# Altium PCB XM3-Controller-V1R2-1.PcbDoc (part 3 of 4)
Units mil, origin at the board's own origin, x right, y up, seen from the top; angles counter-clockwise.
Board outline 10629.92 x 4173.11 mil, 6 copper layers (TOP, GND1, LAYER3, PWR, GND2, BOTTOM), stack 62 mil thick; 362 components, 276 nets, 1145 pads, 503 vias.
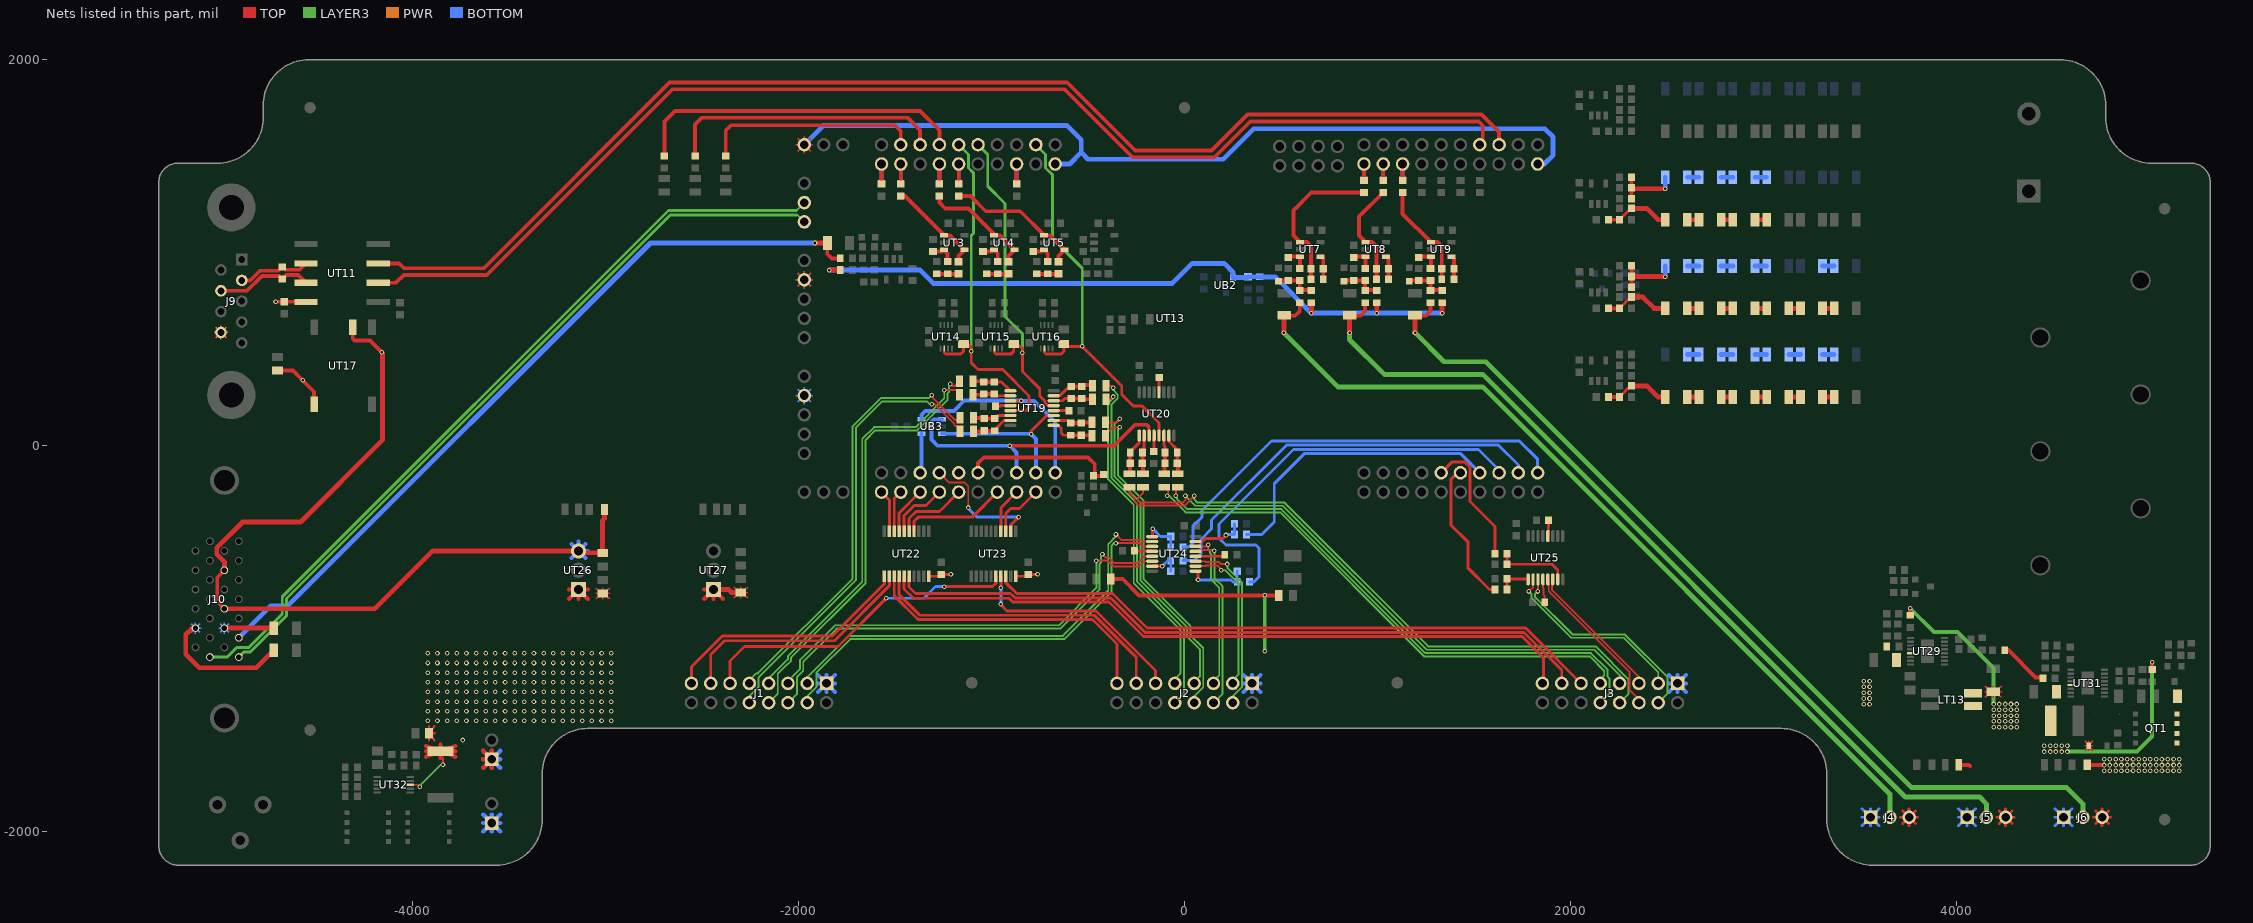
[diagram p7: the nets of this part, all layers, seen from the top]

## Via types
v1: diameter 24, hole 13, TOP to BOTTOM, 503 vias

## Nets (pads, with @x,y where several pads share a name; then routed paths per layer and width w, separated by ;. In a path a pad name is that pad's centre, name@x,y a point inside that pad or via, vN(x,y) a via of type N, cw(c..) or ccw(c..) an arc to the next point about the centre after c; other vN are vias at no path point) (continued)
+3VREF: CB15.1 RB20.1 RT49.1 RT63.1 RT65.1 RT67.1 UB2.2 | length 3589.5
  TOP w25: v1(-1840,910) -1839.36,910.64 -1837.69,910.64 RT49.1@-1784,910.64 ; v1(657.5,687.5) RT63.1@657.5,741.19 ; v1(996.02,687.5) RT65.1@996.02,741.19 ; v1(1334.54,687.5) RT67.1@1334.54,741.19
  BOTTOM w25: v1(-1840,910) -1369.99,910 -1299.99,840 -65,840 40,945 205,945 251.25,898.75 UB2.2@251.25,872.16 325.75,872.16 CB15.1@329.25,875.66 RB20.1@389.25,875.66 389.91,875 470,875 v1(657.5,687.5) v1(996.02,687.5) v1(1334.54,687.5)
+5V: CT63.1 CT65.1 CT66.1 J10.12 J10.20 RT109.1 UT13.21 UT13.61 UT13.92 UT13.97 UT13.105 UT17.2 UT22.20 UT23.20 UT26.3 | length 10975.7
  TOP w7: -2014.02,860 UT13.97@-1970,860 ; -2014.02,1560 UT13.105@-1970,1560 ; -2003.13,826.87 UT13.97@-1970,860 ; -2003.13,893.13 UT13.97@-1970,860 ; -2003.13,1526.87 UT13.105@-1970,1560 ; -2003.13,1593.13 UT13.105@-1970,1560 ; -1970,815.98 UT13.97@-1970,860 ; -1970,904.02 UT13.97@-1970,860 ; -1970,1515.98 UT13.105@-1970,1560 ; -1970,1604.02 UT13.105@-1970,1560 ; -1936.87,826.87 UT13.97@-1970,860 ; -1936.87,893.13 UT13.97@-1970,860 ; -1936.87,1526.87 UT13.105@-1970,1560 ; -1936.87,1593.13 UT13.105@-1970,1560 ; -1925.98,860 UT13.97@-1970,860 ; -1925.98,1560 UT13.105@-1970,1560
  TOP w15: UT22.20@-1324.84,-676.14 -1269.64,-676.14 CT65.1@-1260,-666.5 v1(-1210,-666.5) ; UT23.20@-874.84,-676.14 -819.64,-676.14 CT66.1@-810,-666.5 v1(-761.5,-666.5)
  TOP w20: J10.12@-4975,-845 -5012,-808 -5012,-682 J10.20@-4975,-645 ; UT17.2@-4310,615 -4310,555 -4300,545 -4220,545 v1(-4160,485)
  TOP w25: J10.12@-4975,-845 -4195,-845 -3895,-545 UT26.3@-3140.47,-545 -3130.9,-554.57 CT63.1@-3015,-554.57 -3015,-386.43 -3005.63,-377.06 RT109.1@-3005.63,-330 ; J10.20@-4975,-645 -4975,-600.87 -5014.5,-561.37 -5014.5,-528.63 -4880.87,-395 -4580,-395 -4155,30 -4155,480 v1(-4160,485)
  BOTTOM w7: -2014.02,260 UT13.92@-1970,260 ; -2014.02,860 UT13.97@-1970,860 ; -2003.13,226.87 UT13.92@-1970,260 ; -2003.13,293.13 UT13.92@-1970,260 ; -2003.13,826.87 UT13.97@-1970,860 ; -2003.13,893.13 UT13.97@-1970,860 ; -1970,215.98 UT13.92@-1970,260 ; -1970,304.02 UT13.92@-1970,260 ; -1970,815.98 UT13.97@-1970,860 ; -1970,904.02 UT13.97@-1970,860 ; -1936.87,226.87 UT13.92@-1970,260 ; -1936.87,293.13 UT13.92@-1970,260 ; -1936.87,826.87 UT13.97@-1970,860 ; -1936.87,893.13 UT13.97@-1970,860 ; -1925.98,260 UT13.92@-1970,260 ; -1925.98,860 UT13.97@-1970,860
  BOTTOM w22: -3188.86,-545 UT26.3@-3140.47,-545 ; -3176.69,-581.22 UT26.3@-3140.47,-545 ; -3176.69,-508.78 UT26.3@-3140.47,-545 ; -3140.47,-496.61 UT26.3@-3140.47,-545 ; -3104.25,-581.22 UT26.3@-3140.47,-545 ; -3104.25,-508.78 UT26.3@-3140.47,-545 ; -3092.08,-545 UT26.3@-3140.47,-545
  BOTTOM w25: UT13.105@-1970,1560 -1870,1660 -610,1660 -535,1585 -535,1520 ; UT13.61@-670,1460 -595,1460 -535,1520 ; UT13.21@1830,1460 1865,1460 1910,1505 1910,1600 1867.32,1642.68 357.68,1642.68 200,1485 -500,1485 -535,1520
+5V-ISO: CT37.1 CT47.1 J9.9 UT11.8 UT17.5 | length 766
  TOP w20: v1(-4710,746.5) CT37.1@-4665,746.5 -4554,746.5 UT11.8@-4552.5,745 ; CT47.1@-4700,389.57 -4619.57,389.57 v1(-4569.47,339.47) -4510,280 UT17.5@-4510,215 UT17.5@-4510,195
  PWR w7: -5027.52,587 J9.9@-4993,587 ; -5019.41,560.59 J9.9@-4993,587 ; -5019.41,613.41 J9.9@-4993,587 ; -4993,552.48 J9.9@-4993,587 ; -4993,621.52 J9.9@-4993,587 ; -4966.59,560.59 J9.9@-4993,587 ; -4966.59,613.41 J9.9@-4993,587 ; -4958.48,587 J9.9@-4993,587
+12V: CT68.1 CT70.1 CT78.1 CT83.1 CT86.1 DT10.A J1.1 J2.1 J3.1 J12.1 J13.1 LT13.1 LT14.1 RT116.1 RT119.1 RT125.1 RT128.2 RT132.2 RT133.1 RT141.2 UT26.1 UT27.1 UT29.5 UT31.5 UT32.8 | length 7205.2
  TOP w7: -3051.58,-792.87 CT70.1@-3015,-765.43 ; -3051.58,-765.43 CT70.1@-3015,-765.43 ; -3051.58,-737.99 CT70.1@-3015,-765.43 ; -3015,-795.12 CT70.1@-3015,-765.43 ; -3015,-735.74 CT70.1@-3015,-765.43 ; -2978.42,-792.87 CT70.1@-3015,-765.43 ; -2978.42,-765.43 CT70.1@-3015,-765.43 ; -2978.42,-737.99 CT70.1@-3015,-765.43 ; -2336.58,-787.87 CT68.1@-2300,-760.43 ; -2336.58,-732.99 CT68.1@-2300,-760.43 ; -2300,-790.12 CT68.1@-2300,-760.43 ; -2300,-730.74 CT68.1@-2300,-760.43 ; -2263.42,-787.87 CT68.1@-2300,-760.43 ; -2263.42,-760.43 CT68.1@-2300,-760.43 ; -2263.42,-732.99 CT68.1@-2300,-760.43 ; 4664.48,-1555 DT10.A@4686,-1555 ; 4666.66,-1580.52 DT10.A@4686,-1555 ; 4666.66,-1529.48 DT10.A@4686,-1555 ; 4686,-1580.52 DT10.A@4686,-1555 ; 4686,-1529.48 DT10.A@4686,-1555 ; 4705.34,-1580.52 DT10.A@4686,-1555 ; 4705.34,-1529.48 DT10.A@4686,-1555 ; 4707.52,-1555 DT10.A@4686,-1555
  TOP w10: UT32.8@-4012.5,-1756.67 -3972.5,-1756.67 v1(-3962.5,-1766.67) ; v1(-3842.5,-1653.33) -3842.5,-1618.2
  TOP w12: -3914.57,-1526.58 CT86.1@-3914.57,-1490 ; -3914.57,-1453.42 CT86.1@-3914.57,-1490 ; -3887.13,-1526.58 CT86.1@-3914.57,-1490 ; -3887.13,-1453.42 CT86.1@-3914.57,-1490 ; -3884.88,-1490 CT86.1@-3914.57,-1490
  TOP w20: RT116.1@-382.6,-690 -320,-690 -235,-775 v1(416.11,-775) RT119.1@487.6,-775 ; RT128.2@4250.5,-1059 4269,-1059 4410,-1200 4443.5,-1200 RT133.1@4448.5,-1205 ; RT132.2@5014,-1159.5 v1(5014,-1121)
  TOP w22: -3930.95,-1611.18 RT141.2@-3855,-1583.25 ; -3930.95,-1583.25 RT141.2@-3855,-1583.25 ; -3930.95,-1555.32 RT141.2@-3855,-1583.25 ; -3855,-1616.88 RT141.2@-3855,-1583.25 ; -3855,-1549.62 RT141.2@-3855,-1583.25 ; -3779.05,-1611.18 RT141.2@-3855,-1583.25 ; -3779.05,-1583.25 RT141.2@-3855,-1583.25 ; -3779.05,-1555.32 RT141.2@-3855,-1583.25 ; -3634.02,-1669.02 J13.1@-3590,-1625 ; -3634.02,-1625 J13.1@-3590,-1625 ; -3634.02,-1580.98 J13.1@-3590,-1625 ; -3590,-1669.02 J13.1@-3590,-1625 ; -3590,-1580.98 J13.1@-3590,-1625 ; -3188.86,-793.39 UT26.1@-3140.47,-745 ; -3188.86,-745 UT26.1@-3140.47,-745 ; -3140.47,-793.39 UT26.1@-3140.47,-745 ; -3092.08,-793.39 UT26.1@-3140.47,-745 ; -3092.08,-745 UT26.1@-3140.47,-745 ; -2488.86,-793.39 UT27.1@-2440.47,-745 ; -2488.86,-745 UT27.1@-2440.47,-745 ; -2440.47,-793.39 UT27.1@-2440.47,-745 ; -2392.08,-793.39 UT27.1@-2440.47,-745
  TOP w25: UT27.1@-2440.47,-745 -2362.49,-745 -2347.06,-760.43 CT68.1@-2300,-760.43
  LAYER3 w10: v1(-3962.5,-1766.67) -3962.5,-1761.67 -3854.16,-1653.33 v1(-3842.5,-1653.33)
  LAYER3 w20: v1(416.11,-1063.89) v1(416.11,-775) ; v1(4575.37,-1584.56) 4575.81,-1585 4935,-1585 5014,-1506 v1(5014,-1121)
  BOTTOM w22: -3634.02,-1999.02 J12.1@-3590,-1955 ; -3634.02,-1955 J12.1@-3590,-1955 ; -3634.02,-1910.98 J12.1@-3590,-1955 ; -3634.02,-1669.02 J13.1@-3590,-1625 ; -3634.02,-1625 J13.1@-3590,-1625 ; -3634.02,-1580.98 J13.1@-3590,-1625 ; -3590,-1999.02 J12.1@-3590,-1955 ; -3590,-1910.98 J12.1@-3590,-1955 ; -3590,-1669.02 J13.1@-3590,-1625 ; -3590,-1580.98 J13.1@-3590,-1625 ; -3545.98,-1999.02 J12.1@-3590,-1955 ; -3545.98,-1955 J12.1@-3590,-1955 ; -3545.98,-1910.98 J12.1@-3590,-1955 ; -3545.98,-1669.02 J13.1@-3590,-1625 ; -3545.98,-1625 J13.1@-3590,-1625 ; -3545.98,-1580.98 J13.1@-3590,-1625 ; -1898.74,-1275.38 J1.1@-1854.72,-1231.36 ; -1898.74,-1231.36 J1.1@-1854.72,-1231.36 ; -1898.74,-1187.34 J1.1@-1854.72,-1231.36 ; -1854.72,-1275.38 J1.1@-1854.72,-1231.36 ; -1854.72,-1187.34 J1.1@-1854.72,-1231.36 ; -1810.7,-1275.38 J1.1@-1854.72,-1231.36 ; -1810.7,-1231.36 J1.1@-1854.72,-1231.36 ; -1810.7,-1187.34 J1.1@-1854.72,-1231.36 ; 305.98,-1275.38 J2.1@350,-1231.36 ; 305.98,-1231.36 J2.1@350,-1231.36 ; 305.98,-1187.34 J2.1@350,-1231.36 ; 350,-1275.38 J2.1@350,-1231.36 ; 350,-1187.34 J2.1@350,-1231.36 ; 394.02,-1275.38 J2.1@350,-1231.36 ; 394.02,-1231.36 J2.1@350,-1231.36 ; 394.02,-1187.34 J2.1@350,-1231.36 ; 2510.7,-1275.38 J3.1@2554.72,-1231.36 ; 2510.7,-1231.36 J3.1@2554.72,-1231.36 ; 2510.7,-1187.34 J3.1@2554.72,-1231.36 ; 2554.72,-1275.38 J3.1@2554.72,-1231.36 ; 2554.72,-1187.34 J3.1@2554.72,-1231.36 ; 2598.74,-1275.38 J3.1@2554.72,-1231.36 ; 2598.74,-1231.36 J3.1@2554.72,-1231.36 ; 2598.74,-1187.34 J3.1@2554.72,-1231.36
  other v1: 4455.37,-1584.56 4485.37,-1584.56 4515.37,-1584.56 4545.37,-1584.56 4455.37,-1554.56 4485.37,-1554.56 4515.37,-1554.56 4545.37,-1554.56 4575.37,-1554.56 -3740,-1525 -3920.82,-1425.62 -3870.82,-1425.62 -3820.82,-1425.62 -3770.82,-1425.62 -3720.82,-1425.62 -3670.82,-1425.62 -3620.82,-1425.62 -3570.82,-1425.62 -3520.82,-1425.62 -3470.82,-1425.62 -3420.82,-1425.62 -3370.82,-1425.62 -3320.82,-1425.62 -3270.82,-1425.62 -3220.82,-1425.62 -3170.82,-1425.62 -3120.82,-1425.62 -3070.82,-1425.62 -3020.82,-1425.62 -2970.82,-1425.62 -3920.82,-1375.62 -3870.82,-1375.62 -3820.82,-1375.62 -3770.82,-1375.62 -3720.82,-1375.62 -3670.82,-1375.62 -3620.82,-1375.62 -3570.82,-1375.62 -3520.82,-1375.62 -3470.82,-1375.62 -3420.82,-1375.62 -3370.82,-1375.62 -3320.82,-1375.62 -3270.82,-1375.62 -3220.82,-1375.62 -3170.82,-1375.62 -3120.82,-1375.62 -3070.82,-1375.62 -3020.82,-1375.62 -2970.82,-1375.62 3519.56,-1339.63 3549.56,-1339.63 -3920.82,-1325.62 -3870.82,-1325.62 -3820.82,-1325.62 -3770.82,-1325.62 -3720.82,-1325.62 -3670.82,-1325.62 -3620.82,-1325.62 -3570.82,-1325.62 -3520.82,-1325.62 -3470.82,-1325.62 -3420.82,-1325.62 -3370.82,-1325.62 -3320.82,-1325.62 -3270.82,-1325.62 -3220.82,-1325.62 -3170.82,-1325.62 -3120.82,-1325.62 -3070.82,-1325.62 -3020.82,-1325.62 -2970.82,-1325.62 3519.56,-1309.63 3549.56,-1309.63 3519.56,-1279.63 3549.56,-1279.63 -3920.82,-1275.62 -3870.82,-1275.62 -3820.82,-1275.62 -3770.82,-1275.62 -3720.82,-1275.62 -3670.82,-1275.62 -3620.82,-1275.62 -3570.82,-1275.62 -3520.82,-1275.62 -3470.82,-1275.62 -3420.82,-1275.62 -3370.82,-1275.62 -3320.82,-1275.62 -3270.82,-1275.62 -3220.82,-1275.62 -3170.82,-1275.62 -3120.82,-1275.62 -3070.82,-1275.62 -3020.82,-1275.62 -2970.82,-1275.62 3519.56,-1249.63 3549.56,-1249.63 -3920.82,-1225.62 -3870.82,-1225.62 -3820.82,-1225.62 -3770.82,-1225.62 -3720.82,-1225.62 -3670.82,-1225.62 -3620.82,-1225.62 -3570.82,-1225.62 -3520.82,-1225.62 -3470.82,-1225.62 -3420.82,-1225.62 -3370.82,-1225.62 -3320.82,-1225.62 -3270.82,-1225.62 -3220.82,-1225.62 -3170.82,-1225.62 -3120.82,-1225.62 -3070.82,-1225.62 -3020.82,-1225.62 -2970.82,-1225.62 3519.56,-1219.63 3549.56,-1219.63 -3920.82,-1175.62 -3870.82,-1175.62 -3820.82,-1175.62 -3770.82,-1175.62 -3720.82,-1175.62 -3670.82,-1175.62 -3620.82,-1175.62 -3570.82,-1175.62 -3520.82,-1175.62 -3470.82,-1175.62 -3420.82,-1175.62 -3370.82,-1175.62 -3320.82,-1175.62 -3270.82,-1175.62 -3220.82,-1175.62 -3170.82,-1175.62 -3120.82,-1175.62 -3070.82,-1175.62 -3020.82,-1175.62 -2970.82,-1175.62 -3920.82,-1125.62 -3870.82,-1125.62 -3820.82,-1125.62 -3770.82,-1125.62 -3720.82,-1125.62 -3670.82,-1125.62 -3620.82,-1125.62 -3570.82,-1125.62 -3520.82,-1125.62 -3470.82,-1125.62 -3420.82,-1125.62 -3370.82,-1125.62 -3320.82,-1125.62 -3270.82,-1125.62 -3220.82,-1125.62 -3170.82,-1125.62 -3120.82,-1125.62 -3070.82,-1125.62 -3020.82,-1125.62 -2970.82,-1125.62 -3920.82,-1075.62 -3870.82,-1075.62 -3820.82,-1075.62 -3770.82,-1075.62 -3720.82,-1075.62 -3670.82,-1075.62 -3620.82,-1075.62 -3570.82,-1075.62 -3520.82,-1075.62 -3470.82,-1075.62 -3420.82,-1075.62 -3370.82,-1075.62 -3320.82,-1075.62 -3270.82,-1075.62 -3220.82,-1075.62 -3170.82,-1075.62 -3120.82,-1075.62 -3070.82,-1075.62 -3020.82,-1075.62 -2970.82,-1075.62
+15V: CT72.1 CT85.1 J4.1 J5.1 J6.1 J10.8 QT1.5 QT1.6 QT1.7 QT1.8 RT138.1 | length 1862.3
  TOP w20: RT138.1@4677.75,-1653.47 4764.09,-1653.47 v1(4764.95,-1654.33)
  TOP w25: J10.8@-4975,-945 CT72.1@-4719.06,-945
  BOTTOM w7: -5004.02,-945 J10.8@-4975,-945 ; -4997.52,-967.52 J10.8@-4975,-945 ; -4997.52,-922.48 J10.8@-4975,-945 ; -4975,-974.02 J10.8@-4975,-945 ; -4975,-915.98 J10.8@-4975,-945 ; -4952.48,-967.52 J10.8@-4975,-945 ; -4952.48,-922.48 J10.8@-4975,-945 ; -4945.98,-945 J10.8@-4975,-945
  BOTTOM w15: 3510.98,-1969.02 J4.1@3555,-1925 ; 3510.98,-1925 J4.1@3555,-1925 ; 3510.98,-1880.98 J4.1@3555,-1925 ; 3555,-1969.02 J4.1@3555,-1925 ; 3555,-1880.98 J4.1@3555,-1925 ; 3599.02,-1969.02 J4.1@3555,-1925 ; 3599.02,-1925 J4.1@3555,-1925 ; 3599.02,-1880.98 J4.1@3555,-1925 ; 4010.98,-1969.02 J5.1@4055,-1925 ; 4010.98,-1925 J5.1@4055,-1925 ; 4010.98,-1880.98 J5.1@4055,-1925 ; 4055,-1969.02 J5.1@4055,-1925 ; 4055,-1880.98 J5.1@4055,-1925 ; 4099.02,-1969.02 J5.1@4055,-1925 ; 4099.02,-1925 J5.1@4055,-1925 ; 4099.02,-1880.98 J5.1@4055,-1925 ; 4510.98,-1969.02 J6.1@4555,-1925 ; 4510.98,-1925 J6.1@4555,-1925 ; 4510.98,-1880.98 J6.1@4555,-1925 ; 4555,-1969.02 J6.1@4555,-1925 ; 4555,-1880.98 J6.1@4555,-1925 ; 4599.02,-1969.02 J6.1@4555,-1925 ; 4599.02,-1925 J6.1@4555,-1925 ; 4599.02,-1880.98 J6.1@4555,-1925
  other v1: 4764.95,-1684.33 4794.95,-1684.33 4824.95,-1684.33 4854.95,-1684.33 4884.95,-1684.33 4914.95,-1684.33 4944.95,-1684.33 4974.95,-1684.33 5004.95,-1684.33 5034.95,-1684.33 5064.95,-1684.33 5094.95,-1684.33 5124.95,-1684.33 5154.95,-1684.33 4794.95,-1654.33 4824.95,-1654.33 4854.95,-1654.33 4884.95,-1654.33 4914.95,-1654.33 4944.95,-1654.33 4974.95,-1654.33 5004.95,-1654.33 5034.95,-1654.33 5064.95,-1654.33 5094.95,-1654.33 5124.95,-1654.33 5154.95,-1654.33 4764.95,-1624.33 4794.95,-1624.33 4824.95,-1624.33 4854.95,-1624.33 4884.95,-1624.33 4914.95,-1624.33 4944.95,-1624.33 4974.95,-1624.33 5004.95,-1624.33 5034.95,-1624.33 5064.95,-1624.33 5094.95,-1624.33 5124.95,-1624.33 5154.95,-1624.33
-15V: CT76.1 CT81.1 DT11.2 J4.3 J5.3 J6.3 J10.7 LT13.2 RT121.2 | length 3229.7
  TOP w7: 4145.54,-1302.47 CT81.1@4190,-1274.06 ; 4145.54,-1274.06 CT81.1@4190,-1274.06 ; 4145.54,-1245.65 CT81.1@4190,-1274.06 ; 4190,-1305.72 CT81.1@4190,-1274.06 ; 4190,-1242.4 CT81.1@4190,-1274.06 ; 4234.46,-1302.47 CT81.1@4190,-1274.06 ; 4234.46,-1274.06 CT81.1@4190,-1274.06 ; 4234.46,-1245.65 CT81.1@4190,-1274.06
  TOP w15: 3710.98,-1925 J4.3@3755,-1925 ; 3721.87,-1958.13 J4.3@3755,-1925 ; 3721.87,-1891.87 J4.3@3755,-1925 ; 3755,-1969.02 J4.3@3755,-1925 ; 3755,-1880.98 J4.3@3755,-1925 ; 3788.13,-1958.13 J4.3@3755,-1925 ; 3788.13,-1891.87 J4.3@3755,-1925 ; 3799.02,-1925 J4.3@3755,-1925 ; 4210.98,-1925 J5.3@4255,-1925 ; 4221.87,-1958.13 J5.3@4255,-1925 ; 4221.87,-1891.87 J5.3@4255,-1925 ; 4255,-1969.02 J5.3@4255,-1925 ; 4255,-1880.98 J5.3@4255,-1925 ; 4288.13,-1958.13 J5.3@4255,-1925 ; 4288.13,-1891.87 J5.3@4255,-1925 ; 4299.02,-1925 J5.3@4255,-1925 ; 4710.98,-1925 J6.3@4755,-1925 ; 4721.87,-1958.13 J6.3@4755,-1925 ; 4721.87,-1891.87 J6.3@4755,-1925 ; 4755,-1969.02 J6.3@4755,-1925 ; 4755,-1880.98 J6.3@4755,-1925 ; 4788.13,-1958.13 J6.3@4755,-1925 ; 4788.13,-1891.87 J6.3@4755,-1925 ; 4799.02,-1925 J6.3@4755,-1925
  TOP w20: RT121.2@3760,-878.5 v1(3760,-841.78) ; DT11.2@4012,-1653.47 4063.47,-1653.47 4070,-1660
  TOP w25: J10.7@-5125,-945 -5141.99,-945 -5175,-978.01 -5175,-1080 -5105,-1150 -4809.06,-1150 CT76.1@-4719.06,-1060
  LAYER3 w20: v1(3760,-841.78) 3883.22,-965 4005,-965 4192.51,-1152.51 v1(4192.51,-1338.45)
  BOTTOM w7: -5154.02,-945 J10.7@-5125,-945 ; -5147.52,-967.52 J10.7@-5125,-945 ; -5147.52,-922.48 J10.7@-5125,-945 ; -5125,-974.02 J10.7@-5125,-945 ; -5125,-915.98 J10.7@-5125,-945 ; -5102.48,-967.52 J10.7@-5125,-945 ; -5102.48,-922.48 J10.7@-5125,-945 ; -5095.98,-945 J10.7@-5125,-945
  other v1: 4192.51,-1458.45 4222.51,-1458.45 4252.51,-1458.45 4282.51,-1458.45 4312.51,-1458.45 4192.51,-1428.45 4222.51,-1428.45 4252.51,-1428.45 4282.51,-1428.45 4312.51,-1428.45 4192.51,-1398.45 4222.51,-1398.45 4252.51,-1398.45 4282.51,-1398.45 4312.51,-1398.45 4192.51,-1368.45 4222.51,-1368.45 4252.51,-1368.45 4282.51,-1368.45 4312.51,-1368.45 4222.51,-1338.45 4252.51,-1338.45 4282.51,-1338.45 4312.51,-1338.45
A-CURRENT: CB7.1 RT15.2 UT13.30 | length 166.5
  TOP w20: RT15.2@930,1375 UT13.30@930,1460
  BOTTOM w20: CB7.1@930,1378.5 UT13.30@930,1460
A-FAULT: UB3.6 UT13.80 UT19.3 | length 1113.3
  TOP w15: UT19.3@-902.2,233.39 -901.65,232.84 v1(-845,232.84)
  BOTTOM w20: UB3.6@-1363.5,137.5 -1363.5,160 -1343.5,180 -1195,180 -1141,234 -846.16,234 v1(-845,232.84) -779.45,232.84 -670,123.39 UT13.80@-670,-140
A-FAULT-N: J1.8 LT1.1 | length 2229.5
  TOP w10: v1(-1212.99,320.01) -1203.4,310.42 -1189.25,310.42 LT1.1@-1165.5,334.17
  LAYER3 w10: J1.8@-2154.72,-1331.36 -2107.72,-1284.36 -2107.72,-1192.65 -2107.66,-1192.59 -2107.62,-1181.85 -2073,-1147.43 -2038,-1114.06 -2038,-1097.05 -1653,-712.05 -1653,28.43 -1601.43,80 -1385.95,80 -1228,237.95 -1228,271.05 -1221,278.05 -1221,312 v1(-1212.99,320.01)
A-FAULT-N-FILTER: CT52.2 LT1.2 RT91.2 UT19.1 | length 213.8
  TOP w15: RT91.2@-985.5,330.67 -948.3,330.67 UT19.1@-902.2,284.57
  TOP w20: LT1.2@-1095.5,334.17 -1044,334.17 CT52.2@-1040.5,330.67 RT91.2@-985.5,330.67
A-FAULT-P: J1.7 LT3.1 | length 2119.6
  TOP w10: v1(-1245,288) -1176.83,288 -1165.5,276.67 LT3.1@-1165.5,264.17
  LAYER3 w10: J1.7@-2154.72,-1231.36 -2154.72,-1204.72 -2085.43,-1135.78 -2055,-1106.77 -2055,-1090 -1670,-705 -1670,35.48 -1608.48,97 -1393,97 -1245,245 v1(-1245,288)
A-FAULT-P-FILTER: CT52.1 LT3.2 RT91.1 UT19.2 | length 198.3
  TOP w15: RT91.1@-985.5,267.67 -976.81,258.98 UT19.2@-902.2,258.98
  TOP w20: LT3.2@-1095.5,264.17 -1044,264.17 CT52.1@-1040.5,267.67 RT91.1@-985.5,267.67
A-LEN: J1.13 UT22.12 | length 1272.3
  TOP w15: J1.13@-2454.72,-1231.36 -2454.72,-1080.91 -2384.4,-1010.59 -1814.4,-1010.59 -1529.57,-725.76 UT22.12@-1529.57,-676.14
A-LEN-OUT: UT13.52 UT22.8 | length 217.9
  TOP w15: UT22.8@-1503.98,-443.86 -1503.98,-273.98 UT13.52@-1470,-240
A-OCEN: J1.15 UT22.11 | length 1303.1
  TOP w15: J1.15@-2554.72,-1231.36 -2554.72,-1144.72 -2395,-985 -1825,-985 -1555.16,-715.16 UT22.11@-1555.16,-676.14
A-OCEN-OUT: UT13.51 UT22.9 | length 220.6
  TOP w15: UT13.51@-1570,-240 -1529.57,-280.43 UT22.9@-1529.57,-443.86
A-PSDIS: J1.11 UT23.16 | length 1696.9
  TOP w15: J1.11@-2354.72,-1231.36 -2354.72,-1114.72 -2280,-1040 -1795,-1040 v1(-1545,-790) ; v1(-1245,-730) -995,-730 -977.2,-712.2 UT23.16@-977.2,-676.14
  BOTTOM w15: v1(-1545,-790) -1350,-790 -1290,-730 v1(-1245,-730)
A-PSDIS-OUT: UT13.58 UT23.4 | length 237.7
  TOP w15: UT23.4@-951.61,-443.86 -951.61,-321.61 UT13.58@-870,-240
A-RTD: RT84.1 UT13.46 UT14.2 UT19.5 | length 1937
  TOP w10: -1245,483.49 UT14.2@-1245,504
  TOP w15: -1245,483.49 -1236.01,474.5 -1160,474.5 -1145,489.5 RT84.1@-1145,518.32 ; RT84.1@-1145,527.6 RT84.1@-1145,518.32 ; UT19.5@-902.2,182.2 -820,182.2 -805,197.2 -805,258.19 -941.81,395 -1070,395 -1105,430 v1(-1105,488.91) -1105,507.96 -1120,522.96 -1140.36,522.96 RT84.1@-1145,518.32
  LAYER3 w15: UT13.46@-1170,1560 -1119.5,1509.5 -1119.5,1439.49 -1094.39,1414.38 -1094.39,1100.61 -1105,1090 v1(-1105,488.91)
A-RTD-N: J1.10 LT7.1 | length 2325.1
  TOP w10: v1(-1310,215.87) -1294.92,215.87 -1195.46,116.41 -1193.24,116.41 -1193,116.17 -1193,109.19 -1185.98,102.17 -1179,102.17 -1163.5,86.67 LT7.1@-1163.5,74.17
  LAYER3 w10: J1.10@-2254.72,-1331.36 -2254.72,-1297.83 -2207.72,-1250.83 -2207.72,-1200.89 -1703,-696.17 -1703,92.95 -1565.95,230 -1335.01,230 -1320.88,215.87 v1(-1310,215.87)
A-RTD-N-FILTER: CT55.2 LT7.2 RT102.2 UT19.7 | length 217.8
  TOP w15: RT102.2@-983.5,77.67 -983.5,82.76 -935.24,131.02 UT19.7@-902.2,131.02
  TOP w20: LT7.2@-1093.5,74.17 -1042,74.17 CT55.2@-1038.5,77.67 RT102.2@-983.5,77.67
A-RTD-P: J1.9 LT5.1 | length 2242.4
  TOP w10: v1(-1310,261.13) -1310,255 -1188.41,133.41 -1174.26,133.41 LT5.1@-1163.5,144.17
  LAYER3 w10: J1.9@-2254.72,-1231.36 -2254.72,-1214.72 -2220,-1180 -2210.88,-1180 -1720,-689.12 -1720,100 -1573,247 -1324.13,247 v1(-1310,261.13)
A-RTD-P-FILTER: CT55.1 LT5.2 RT102.1 UT19.6 | length 199.4
  TOP w15: RT102.1@-983.5,140.67 -967.56,156.61 UT19.6@-902.2,156.61
  TOP w20: LT5.2@-1093.5,144.17 -1042,144.17 CT55.1@-1038.5,140.67 RT102.1@-983.5,140.67
A-TEMP: CB11.1 RT24.2 UT13.69 | length 203.1
  TOP w20: RT24.2@-1470,1356.72 UT13.69@-1470,1460
  BOTTOM w20: CB11.1@-1470,1360.22 UT13.69@-1470,1460
AHS-PWM: RB28.1 UT13.40 | length 2245.9
  BOTTOM w15: RB28.1@-8.5,-525 20,-525 45,-500 45,-415 90,-370 90,-335.05 450.05,25 1734.99,25 1830,-70.01 UT13.40@1830,-140
AHS-PWM-N: J1.4 UT24.3 | length 2340.3
  TOP w10: v1(-355,-505) -233.02,-505 -216.41,-521.61 UT24.3@-167.2,-521.61
  LAYER3 w10: J1.4@-1954.72,-1331.36 -1954.72,-1297.83 -1907.72,-1250.83 -1907.72,-1176.77 -1732.95,-1002 -622.95,-1002 -378,-757.05 -378,-517.05 -365.95,-505 v1(-355,-505)
AHS-PWM-P: J1.3 UT24.2 | length 2287.9
  TOP w10: v1(-355,-459.74) -326.74,-488 -225.97,-488 -217.18,-496.79 -216.4,-496.02 UT24.2@-167.2,-496.02
  LAYER3 w10: J1.3@-1954.72,-1231.36 -1954.72,-1199.72 -1740,-985 -630,-985 -395,-750 -395,-510 -355,-470 v1(-355,-459.74)
ALS-PWM: RB29.1 UT13.39 | length 2139.2
  BOTTOM w15: RB29.1@-8.5,-595 50,-595 85,-560 85,-485 140,-430 140,-385 528,3 1626.99,3 1730,-100.01 UT13.39@1730,-140
ALS-PWM-N: J1.6 UT24.5 | length 2414
  TOP w10: v1(-425,-562.99) -409.99,-578 -392.95,-578 -362.98,-607.97 -242.98,-607.97 -207.81,-572.8 UT24.5@-167.2,-572.8
  LAYER3 w10: J1.6@-2054.72,-1331.36 -2007.72,-1284.36 -2007.72,-1196.77 -1975.57,-1164.62 -1975.57,-1119.48 -1803.09,-947 -642.95,-947 -440.01,-744.06 -440.01,-611.95 -433.01,-604.95 -433.01,-571 v1(-425,-562.99)
ALS-PWM-P: J1.5 UT24.6 | length 2291
  TOP w10: v1(-457.01,-595) -400,-595 -370.03,-624.97 -235.93,-624.97 -209.35,-598.39 UT24.6@-167.2,-598.39
  LAYER3 w10: J1.5@-2054.72,-1231.36 -2054.72,-1219.72 -1992.57,-1157.57 -1992.57,-1112.43 -1810.14,-930 -650,-930 -457.01,-737.01 v1(-457.01,-595)
B-CURRENT: CB6.1 RT16.2 UT13.29 | length 166.5
  TOP w20: RT16.2@1030,1375 UT13.29@1030,1460
  BOTTOM w20: CB6.1@1030,1378.5 UT13.29@1030,1460
B-FAULT: UB3.3 UT13.79 UT19.11 | length 839.9
  TOP w15: v1(-795,60) -795,75 -713.39,156.61 UT19.11@-677.8,156.61
  BOTTOM w20: UB3.3@-1257.5,62.5 -797.5,62.5 v1(-795,60) -770,35 UT13.79@-770,-140
B-FAULT-N: J2.8 LT8.1 | length 1728.7
  TOP w10: LT8.1@-409.5,50.84 -409.5,56.36 -370.57,95.29 v1(-335.55,95.29)
  LAYER3 w10: v1(-335.55,95.29) -345,85.84 -345,-152.76 -212.09,-285.67 -212.09,-690.76 31,-933.85 31,-981.95 97,-1047.95 97,-1250.83 50,-1297.83 J2.8@50,-1331.36
B-FAULT-N-FILTER: CT56.2 LT8.2 RT103.2 UT19.9 | length 234.2
  TOP w15: UT19.9@-677.8,105.43 -655.16,105.43 -638.64,88.91 -638.64,66.27 -626.71,54.34 RT103.2@-589.5,54.34
  TOP w20: RT103.2@-589.5,54.34 CT56.2@-534.5,54.34 -483,54.34 LT8.2@-479.5,50.84
B-FAULT-P: J2.7 LT6.1 | length 1664.1
  TOP w10: LT6.1@-409.5,120.84 -349.17,120.84 -335.55,134.46 v1(-335.55,140.55)
  LAYER3 w10: v1(-335.55,140.55) -362,114.1 -362,-159.81 -229.09,-292.72 -229.09,-697.81 14,-940.9 14,-989 80,-1055 80,-1195 50,-1225 J2.7@50,-1231.36
B-FAULT-P-FILTER: CT56.1 LT6.2 RT103.1 UT19.10 | length 205.4
  TOP w15: UT19.10@-677.8,131.02 -603.18,131.02 RT103.1@-589.5,117.34
  TOP w20: RT103.1@-589.5,117.34 CT56.1@-534.5,117.34 -531,120.84 LT6.2@-479.5,120.84
B-LEN: J2.13 UT22.14 | length 1593.5
  TOP w15: UT22.14@-1478.39,-676.14 -1478.39,-771.62 -1372.01,-878 -468.12,-878 -250,-1096.12 J2.13@-250,-1231.36
B-LEN-OUT: UT13.54 UT22.6 | length 314.7
  TOP w15: UT22.6@-1452.8,-443.86 -1452.8,-362.8 -1400,-310 -1340,-310 UT13.54@-1270,-240
B-OCEN: J2.15 UT22.13 | length 1562.7
  TOP w15: UT22.13@-1503.98,-676.14 -1503.98,-777.15 -1381.13,-900 -477.24,-900 -350,-1027.24 J2.15@-350,-1231.36
B-OCEN-OUT: UT13.53 UT22.7 | length 248.8
  TOP w15: UT22.7@-1478.39,-443.86 -1478.39,-348.39 UT13.53@-1370,-240
B-PSDIS: J2.11 UT23.17 | length 1156.7
  TOP w15: v1(-951.61,-820) -951.61,-823.38 -918.99,-856 -459,-856 -150,-1165 J2.11@-150,-1231.36 ; v1(-951.61,-735) UT23.17@-951.61,-676.14
  BOTTOM w15: v1(-951.61,-820) v1(-951.61,-735)
B-PSDIS-OUT: UT13.59 UT23.3 | length 294.8
  TOP w15: UT23.3@-926.02,-443.86 -926.02,-351.02 -900,-325 -855,-325 UT13.59@-770,-240
B-RTD: RT85.1 UT13.45 UT15.2 UT19.13 | length 1783.4
  TOP w10: -985,483.49 UT15.2@-985,504
  TOP w15: -985,483.49 -976.01,474.5 -900,474.5 -885,489.5 RT85.1@-885,518.32 ; RT85.1@-880.36,522.96 RT85.1@-885,518.32 ; UT19.13@-677.8,207.8 -700.44,207.8 -702.67,210.03 -710.12,210.03 -723.8,223.71 -723.8,231.16 -750,257.36 -750,295 -840,385 v1(-840,481.97) -840,502.6 -865,527.6 RT85.1@-885,527.6 RT85.1@-885,518.32
  LAYER3 w15: UT13.45@-1070,1560 -1019.5,1509.5 -1019.5,1344.5 -930,1255 -930,670 -840,580 v1(-840,481.97)
B-RTD-N: J2.10 LT2.1 | length 1871.3
  TOP w10: LT2.1@-406.5,310.84 -380.58,310.84 v1(-370,300.26)
  LAYER3 w10: v1(-370,300.26) -370,288.95 -346,264.95 -346,245.05 -379,212.05 -379,-166.86 -246.09,-299.77 -246.09,-704.86 -3,-947.95 -3,-1284.36 J2.10@-50,-1331.36
B-RTD-N-FILTER: CT53.2 LT2.2 RT92.2 UT19.15 | length 226.2
  TOP w15: UT19.15@-677.8,258.98 -646.01,258.98 -597.66,307.34 RT92.2@-586.5,307.34
  TOP w20: RT92.2@-586.5,307.34 CT53.2@-531.5,307.34 -523.84,315 -480.66,315 LT2.2@-476.5,310.84
B-RTD-P: J2.9 LT4.1 | length 1707.7
  TOP w10: LT4.1@-406.5,240.84 -384.16,240.84 v1(-370,255)
  LAYER3 w10: v1(-370,255) -370,245.1 -396,219.1 -396,-173.91 -263.09,-306.82 -263.09,-711.91 -20,-955 -20,-1180 -50,-1210 J2.9@-50,-1231.36
B-RTD-P-FILTER: CT53.1 LT4.2 RT92.1 UT19.14 | length 207.3
  TOP w15: UT19.14@-677.8,233.39 -631.8,233.39 -620.85,244.34 RT92.1@-586.5,244.34
  TOP w20: RT92.1@-586.5,244.34 CT53.1@-531.5,244.34 -528,240.84 LT4.2@-476.5,240.84
B-TEMP: CB10.1 RT25.2 UT13.67 | length 203.1
  TOP w20: RT25.2@-1270,1356.72 UT13.67@-1270,1460
  BOTTOM w20: CB10.1@-1270,1360.22 UT13.67@-1270,1460
BHS-PWM: RB30.1 UT13.38 | length 2179.5
  BOTTOM w15: RB30.1@336.5,-705 360,-705 385,-680 385,-530 370,-515 215,-515 179.19,-479.19 179.19,-405 565.19,-19 1524,-19 1630,-125 UT13.38@1630,-140
BHS-PWM-N: J2.4 UT24.11 | length 939.8
  TOP w10: UT24.11@57.2,-598.39 106.4,-598.39 110.69,-602.68 177.66,-602.68 187.97,-612.99 v1(222.01,-612.99)
  LAYER3 w10: v1(222.01,-612.99) 222.01,-632.96 297,-707.95 297,-1250.83 250,-1297.83 J2.4@250,-1331.36
BHS-PWM-P: J2.3 UT24.10 | length 796.3
  TOP w10: UT24.10@57.2,-623.98 106.39,-623.98 110.69,-619.68 170.61,-619.68 190,-639.07 v1(190,-645)
  LAYER3 w10: v1(190,-645) 210,-645 280,-715 280,-1185 250,-1215 J2.3@250,-1231.36
BLS-PWM: RB27.1 UT13.37 | length 1539.4
  BOTTOM w15: RB27.1@321.5,-460 400,-460 465,-395 465,-196.43 620.43,-41 1430.99,-41 UT13.37@1530,-140
BLS-PWM-N: J2.6 UT24.13 | length 926.1
  TOP w10: UT24.13@57.2,-547.2 61.93,-542.47 88.48,-542.47 90.95,-540 150,-540 v1(155,-545)
  LAYER3 w10: J2.6@150,-1331.36 197,-1284.36 197,-727.95 155,-685.95 v1(155,-545)
BLS-PWM-P: J2.5 UT24.14 | length 830.8
  TOP w10: UT24.14@57.2,-521.61 91.61,-521.61 93,-523 122.99,-523 v1(122.99,-512.99)
  LAYER3 w10: v1(122.99,-512.99) 122.99,-537.99 131,-546 131,-554.95 138,-561.95 138,-693 180,-735 180,-1190 150,-1220 J2.5@150,-1231.36
C-CURRENT: CB5.1 RT17.2 UT13.28 | length 166.5
  TOP w20: RT17.2@1130,1375 UT13.28@1130,1460
  BOTTOM w20: CB5.1@1130,1378.5 UT13.28@1130,1460
C-FAULT: UB3.1 UT13.78 UT20.3 | length 1541.2
  TOP w15: -190,103 -183.39,96.39 UT20.3@-183.39,52.8
  TOP w20: v1(-905,0) -365,0 -256.36,108.64 -195.64,108.64 -190,103
  BOTTOM w20: UB3.1@-1257.5,137.5 -1297.5,137.5 -1311.65,123.35 -1311.65,31.65 -1280,0 v1(-905,0) -870,-35 UT13.78@-870,-140
C-FAULT-N: J3.8 LT9.1 | length 3218.4
  TOP w10: LT9.1@-285,-215 -285,-244.5 -258.5,-271 -258.5,-290.05 -238.55,-310 0.26,-310 v1(50.26,-260)
  LAYER3 w10: v1(50.26,-260) 50.26,-276.98 67.28,-294 516.14,-294 1262.14,-1040 2129.84,-1040 2301.72,-1211.88 2301.72,-1284.36 J3.8@2254.72,-1331.36
C-FAULT-N-FILTER: CT57.2 LT9.2 RT104.2 UT20.1 | length 218.7
  TOP w15: RT104.2@-281.5,-35 -281.5,-31.49 -234.57,15.44 UT20.1@-234.57,52.8
  TOP w20: LT9.2@-285,-145 -281.5,-141.5 CT57.2@-281.5,-90 RT104.2@-281.5,-35
C-FAULT-P: J3.7 LT10.1 | length 3045.7
  TOP w10: LT10.1@-215,-215 -215,-244.5 -241.5,-271 -241.5,-283 -231.5,-293 -6.79,-293 5,-281.21 v1(5,-260)
  LAYER3 w10: v1(5,-260) 56,-311 509.09,-311 1255.09,-1057 2122.79,-1057 2270.47,-1204.68 2270.47,-1214.52 2254.72,-1230.28 J3.7@2254.72,-1231.36
C-FAULT-P-FILTER: CT57.1 LT10.2 RT104.1 UT20.2 | length 203.2
  TOP w15: RT104.1@-218.5,-35 -218.5,-18.49 -208.98,-8.97 UT20.2@-208.98,52.8
  TOP w20: RT104.1@-218.5,-35 CT57.1@-218.5,-90 -215,-93.5 LT10.2@-215,-145
C-LEN: J3.13 UT22.16 | length 3684.7
  TOP w15: UT22.16@-1427.2,-676.14 -1427.2,-731.59 -1393.79,-765 -901.59,-765 -878.59,-788 -382.85,-788 -203.84,-967.01 1759.25,-967.01 1954.72,-1162.48 J3.13@1954.72,-1231.36
C-LEN-OUT: UT13.57 UT22.4 | length 546.7
  TOP w15: UT22.4@-1401.61,-443.86 -1401.61,-391.61 -1380,-370 -1100,-370 UT13.57@-970,-240
C-OCEN: J3.15 UT22.15 | length 3661.3
  TOP w15: UT22.15@-1452.8,-676.14 -1452.8,-742.2 -1405,-790 -909.99,-790 -889.99,-810 -391.97,-810 -212.96,-989.01 1750.13,-989.01 1860,-1098.88 1860,-1226.08 J3.15@1854.72,-1231.36
C-OCEN-OUT: UT13.55 UT22.5 | length 380.7
  TOP w15: UT22.5@-1427.2,-443.86 -1427.2,-377.2 -1390,-340 -1270,-340 UT13.55@-1170,-240
C-PSDIS: J3.11 UT23.18 | length 3230.2
  TOP w15: UT23.18@-926.02,-676.14 -926.02,-709.45 -869.47,-766 -373.73,-766 -194.73,-945 1768.36,-945 J3.11@2054.72,-1231.36
C-PSDIS-OUT: UT13.74 UT23.2 | length 663.3
  TOP w10: UT13.74@-1270,-140 -1220.5,-189.5 -1140.5,-189.5 -1120.5,-209.5 v1(-1120.5,-320)
  TOP w15: UT23.2@-900.43,-443.86 -900.43,-410.55 v1(-859.94,-370.06)
  BOTTOM w15: v1(-1120.5,-320) -1120.5,-324.5 -1074.94,-370.06 v1(-859.94,-370.06)
C-RTD: RT86.1 UT13.42 UT16.2 UT20.5 | length 2073.4
  TOP w10: -725,483.49 UT16.2@-725,504
  TOP w15: -725,483.49 -716.01,474.5 -640,474.5 -625,489.5 RT86.1@-625,518.32 ; UT20.5@-132.2,52.8 -132.2,117.8 -219.4,205 -265,205 -325,265 -325,310 v1(-530,515) -612.4,515 RT86.1@-620.36,522.96 ; RT86.1@-625,518.32 RT86.1@-625,527.6 RT86.1@-620.36,522.96 ; RT86.1@-625,518.32 RT86.1@-620.36,522.96
  LAYER3 w15: UT13.42@-770,1560 -719.5,1509.5 -719.5,1439.49 -685,1404.99 -685,1075 -530,920 v1(-530,515)
C-RTD-N: J3.10 LT12.1 | length 2859.9
  TOP w10: v1(-45,-260) -45,-225.84 LT12.1@-34.16,-215
  LAYER3 w10: v1(-45,-260) -38,-267 -38,-276.9 13.1,-328 502.04,-328 1248.04,-1074 2105.9,-1074 2192,-1160.1 2192,-1197.05 2201.72,-1206.77 2201.72,-1284.36 J3.10@2154.72,-1331.36
C-RTD-N-FILTER: CT58.2 LT12.2 RT105.2 UT20.7 | length 217.2
  TOP w15: UT20.7@-81.02,52.8 -81.02,22.71 -37.66,-20.65 RT105.2@-37.66,-35
  TOP w20: RT105.2@-37.66,-35 CT58.2@-37.66,-90 -34.16,-93.5 LT12.2@-34.16,-145
C-RTD-P: J3.9 LT11.1 | length 2769.5
  TOP w10: LT11.1@-104.16,-215 -84.13,-235.03 -84.13,-253.87 v1(-90.26,-260)
  LAYER3 w10: v1(-90.26,-260) -78.95,-260 6.05,-345 494.99,-345 1240.99,-1091 2098.85,-1091 2175,-1167.15 2175,-1190 2154.72,-1210.28 J3.9@2154.72,-1231.36
C-RTD-P-FILTER: CT58.1 LT11.2 RT105.1 UT20.6 | length 201.7
  TOP w15: UT20.6@-106.61,52.8 -106.61,1.61 -100.66,-4.34 RT105.1@-100.66,-35
  TOP w20: LT11.2@-104.16,-145 -104.16,-93.5 CT58.1@-100.66,-90 RT105.1@-100.66,-35
C-TEMP: CB9.1 RT26.2 UT13.66 | length 203.1
  TOP w20: RT26.2@-1170,1356.72 UT13.66@-1170,1460
  BOTTOM w20: CB9.1@-1170,1360.22 UT13.66@-1170,1460
CANA-H: J9.7 RT50.1 UT11.7 | length 504.7
  TOP w20: J9.7@-4993,803 -4857.01,803 -4780.01,880 -4691.5,880 RT50.1@-4675,863.5 -4653.5,885 -4592.5,885 UT11.7@-4552.5,845
CANA-L: J9.2 RT50.2 UT11.6 | length 381
  TOP w20: J9.2@-4885,857 -4841.2,857 -4791.2,907 -4696.47,907 -4676.97,926.5 RT50.2@-4675,926.5 -4673.03,926.5 -4667.41,920.88 -4666.05,920.88 -4657.17,912 -4585.5,912 UT11.6@-4552.5,945
CANA-RX: UT11.2 UT13.4 | length 6476.1
  TOP w20: UT11.2@-4177.5,845 -4085,845 -4045,885 -3615.5,885 -2653.2,1847.3 -621.8,1847.3 -269.5,1495 154.5,1495 340.58,1681.08 1524.42,1681.08 1545.25,1660.25 1545.25,1575.25 UT13.4@1530,1560
CANA-TX: UT11.3 UT13.3 | length 6542.2
  TOP w20: UT11.3@-4177.5,945 -4070,945 -4045,920 -3630,920 -2667.7,1882.3 -607.3,1882.3 -255,1530 140,1530 326.08,1716.08 1538.92,1716.08 1630,1625 UT13.3@1630,1560
CANBH: J10.2 UT13.99 | length 3946.9
  LAYER3 w10: -2011.5,1196.5 -2006.51,1196.5 UT13.99@-1970,1160
  LAYER3 w15: J10.2@-4900,-1095 -4872.89,-1067.89 -4839.79,-1067.89 -4653.13,-881.23 -4653.13,-791.45 -2665.18,1196.5 -2011.5,1196.5
CANBL: J10.1 UT13.100 | length 4108.1
  LAYER3 w10: -2011.5,1218.5 UT13.100@-1970,1260
  LAYER3 w15: J10.1@-5050,-1095 -4959.99,-1095 -4910.88,-1045.89 -4848.91,-1045.89 -4675.13,-872.11 -4675.13,-782.33 -2674.3,1218.5 -2011.5,1218.5
CASE-LED1: RT107.1 RT108.1 UT13.76 | length 801.8
  TOP w20: UT13.76@-1070,-140 -1070,-90 -1040,-60 -500,-60 -465,-95 -465,-149.05 RT107.1@-471.79,-155.84 -424.78,-155.84 RT108.1@-418.28,-149.34
CASE-LED2: UT13.75
CASE-TEMP: CB8.1 RT27.2 UT13.63 | length 203.1
  TOP w20: RT27.2@-870,1356.72 UT13.63@-870,1460
  BOTTOM w20: CB8.1@-870,1360.22 UT13.63@-870,1460
CHS-PWM: RT118.1 UT13.36 | length 745.8
  TOP w15: UT13.36@1430,-140 1415,-140 1380,-175 1380,-410 1470,-500 1470,-635 1580,-745 RT118.1@1608.5,-745
CHS-PWM-N: J3.4 UT25.3 | length 1108.3
  TOP w10: v1(1830,-755) 1831.61,-753.39 UT25.3@1831.61,-692.2
  LAYER3 w10: v1(1830,-755) 1815.87,-769.13 1815.87,-783.28 2010.59,-978 2282.05,-978 2501.72,-1197.67 2501.72,-1284.36 J3.4@2454.72,-1331.36
CHS-PWM-P: J3.3 UT25.2 | length 984.5
  TOP w10: v1(1784.74,-755) 1806.02,-733.72 UT25.2@1806.02,-692.2
  LAYER3 w10: v1(1784.74,-755) 1798.87,-769.13 1798.87,-790.33 2003.54,-995 2275,-995 2454.72,-1174.72 J3.3@2454.72,-1231.36
CLS-PWM: RT113.1 UT13.35 | length 686.4
  TOP w15: UT13.35@1330,-140 1385,-85 1455,-85 1479.5,-109.5 1479.5,-289.5 1608.5,-418.5 RT113.1@1608.5,-560
CLS-PWM-N: J3.6 UT25.5 | length 834.6
  TOP w10: UT25.5@1882.8,-692.2 1887.53,-696.93 1887.53,-754.58 2305,-1172.05 2305,-1265 2354.72,-1314.72 J3.6@2354.72,-1331.36
CLS-PWM-P: J3.5 UT25.6 | length 727.2
  TOP w10: UT25.6@1908.39,-692.2 1904.53,-696.06 1904.53,-747.53 2354.72,-1197.72 J3.5@2354.72,-1231.36
EXT-CURRENT: CB12.1 RT23.2 UT13.70 | length 203.1
  TOP w20: RT23.2@-1570,1356.72 UT13.70@-1570,1460
  BOTTOM w20: CB12.1@-1570,1360.22 UT13.70@-1570,1460
GLOBAL-FAULT: UB3.4 UT13.73 | length 205.2
  BOTTOM w20: UT13.73@-1370,-140 -1363.5,-133.5 UB3.4@-1363.5,62.5
IA-M: J4.2 RT62.1 RT72.1 | length 4475.4
  TOP w20: RT72.1@517.5,673.63 573.44,673.63 597.5,697.69 RT62.1@597.5,741.19
  TOP w25: v1(515,585) 515,671.13 517.5,673.63 RT72.1@517.5,675.6
  LAYER3 w25: v1(515,585) 795,305 1545.48,305 3655,-1804.52 J4.2@3655,-1925
IB-M: J5.2 RT64.1 RT73.1 | length 4627.8
  TOP w20: RT73.1@856.02,673.63 911.96,673.63 936.02,697.69 RT64.1@936.02,741.19
  TOP w25: RT73.1@853.52,671.13 RT73.1@855,672.61 ; v1(855,585) RT73.1@855,672.61 ; RT73.1@856.02,675.6 856.02,673.63 RT73.1@855,672.61
  LAYER3 w25: v1(855,585) 855,550 1035,370 1545.48,370 3735.48,-1820 4120,-1820 4155,-1855 J5.2@4155,-1925
IC-M: J6.2 RT66.1 RT74.1 | length 4768.7
  TOP w20: RT74.1@1194.54,673.63 1250.48,673.63 1274.54,697.69 RT66.1@1274.54,741.19
  TOP w25: RT74.1@1192.04,671.13 RT74.1@1194.54,673.63 ; v1(1194.54,585) RT74.1@1194.54,673.63 ; RT74.1@1194.54,675.6 RT74.1@1194.54,673.63
  LAYER3 w25: v1(1194.54,585) 1344.54,435 1560.48,435 3765.48,-1770 4570,-1770 4655,-1855 J6.2@4655,-1925
IEXT-M: J10.6 RT36.1 RT38.1 | length 4034.7
  TOP w20: RT36.1@-1851.56,1050.64 -1851.56,994.7 -1827.5,970.64 RT38.1@-1784,970.64
  TOP w25: v1(-1915,1050.64) RT36.1@-1851.56,1050.64 ; RT36.1@-1854.06,1053.14 RT36.1@-1851.56,1050.64 ; RT36.1@-1849.59,1050.64 RT36.1@-1851.56,1050.64
  BOTTOM w25: J10.6@-4900,-995 -4735,-830 -4647.68,-830 -2767.04,1050.64 v1(-1915,1050.64)
LED-G: RT13.1 UT13.49 | length 1132.9
  TOP w20: RT13.1@-2376.88,1501.5 -2376.88,1633.12 -2349,1661 -1501,1661 -1470,1630 UT13.49@-1470,1560
LED-R: RT11.1 UT13.47 | length 1742.7
  TOP w20: RT11.1@-2695,1501.5 -2695,1680 -2640,1735 -1370,1735 -1270,1635 UT13.47@-1270,1560
LED-Y: RT12.1 UT13.48 | length 1445.3
  TOP w20: RT12.1@-2535.94,1501.5 -2535.94,1664.06 -2500,1700 -1435,1700 -1370,1635 UT13.48@-1370,1560
N07282: RT100.2 UT19.4 | length 77.5
  TOP w15: RT100.2@-978.5,205 -955,205 -952.2,207.8 UT19.4@-902.2,207.8
N07299: RT101.1 UT19.12 | length 79.4
  TOP w15: UT19.12@-677.8,182.2 -630.92,182.2 -630.72,182 RT101.1@-598.5,182
N07508: RT106.2 UT20.4 | length 83.5
  TOP w15: RT106.2@-160,-29.78 -157.8,-27.58 UT20.4@-157.8,52.8
N07516: RT89.1 UT20.12 | length 77.1
  TOP w15: UT20.12@-132.2,277.2 -132.2,351.14 RT89.1@-130,353.34
N07693: RT112.2 UT24.4 | length 92.2
  TOP w15: RT112.2@-258.5,-545 -169.4,-545 UT24.4@-167.2,-547.2
N07878: RT120.2 UT25.4 | length 121.7
  TOP w10: UT25.4@1857.2,-692.2 1857.2,-735.7 1860,-738.5 1860,-771.81 1866.5,-778.31 RT120.2@1866.5,-810
N09835: CB21.1 RB28.2 UT24.1 | length 206.4
  TOP w15: UT24.1@-167.2,-470.43 -165,-468.23 v1(-165,-430)
  BOTTOM w15: v1(-165,-430) -125,-470 CB21.1@-71.5,-470 RB28.2@-71.5,-525
N10049: CB23.1 RB29.2 UT24.7 | length 162.7
  TOP w15: UT24.7@-167.2,-623.98 v1(-115,-623.98)
  BOTTOM w15: v1(-115,-623.98) -86.02,-595 RB29.2@-71.5,-595 CB23.1@-71.5,-650
N10085: CB22.1 RB30.2 UT24.9 | length 314.3
  TOP w15: UT24.9@57.2,-649.57 70,-662.37 v1(70,-695)
  BOTTOM w15: v1(70,-695) 240,-695 251.14,-706.14 272.36,-706.14 RB30.2@273.5,-705 CB22.1@273.5,-650
N10121: CB20.1 RB27.2 UT24.15 | length 271.2
  TOP w15: UT24.15@57.2,-496.02 93.98,-496.02 110,-480 197.72,-480 v1(215,-462.72)
  BOTTOM w15: v1(215,-462.72) 217.72,-460 RB27.2@258.5,-460 CB20.1@258.5,-405
N11382: RT114.2 UT24.12 | length 154.5
  TOP w15: UT24.12@57.2,-572.8 200.7,-572.8 RT114.2@208.5,-565
N11987: RT111.2 UT25.12 | length 84.3
  TOP w15: UT25.12@1882.8,-467.8 1885,-465.6 1885,-420.69 1886.5,-419.19 RT111.2@1886.5,-385
N12714: CT67.1 RT118.2 UT25.1 | length 164.8
  TOP w15: RT118.2@1671.5,-745 CT67.1@1671.5,-690 1778.23,-690 UT25.1@1780.43,-692.2
N12754: CT64.1 RT113.2 UT25.7 | length 378.1
  TOP w15: CT64.1@1671.5,-615 CT64.1@1671.5,-614.01 ; RT113.2@1671.5,-560 CT64.1@1671.5,-614.01 ; UT25.7@1933.98,-692.2 1933.98,-643.98 1904.01,-614.01 CT64.1@1671.5,-614.01
N16187: CT23.2 RT24.1 UT3.1 UT3.4 | length 520.5
  TOP w20: RT24.1@-1470,1293.72 -1448.45,1293.72 -1246.3,1091.57 UT3.1@-1246.3,1089.8 -1214.8,1089.8 UT3.4@-1140,1015 -1171.27,983.73 CT23.2@-1171.27,953.9
N16636: CT23.1 RT41.2 RT42.1 | length 111.9
  TOP w20: RT41.2@-1283.15,890.9 RT42.1@-1227.21,890.9 CT23.1@-1171.27,890.9
N16643: CT15.2 RT42.2 UT3.3 | length 129.6
  TOP w20: CT15.2@-1303.15,1005.9 -1255.4,1005.9 UT3.3@-1246.3,1015 -1227.21,995.91 RT42.2@-1227.21,953.9
N18013: CT24.1 RT43.2 RT44.1 | length 111.9
  TOP w20: RT43.2@-1023.97,890.9 RT44.1@-968.03,890.9 CT24.1@-912.09,890.9
N18021: CT24.2 RT25.1 UT4.1 UT4.4 | length 602.7
  TOP w20: RT25.1@-1270,1293.72 -1270,1260 -1240,1230 -1120,1230 -987.12,1097.12 UT4.1@-987.12,1089.8 -955.62,1089.8 UT4.4@-880.82,1015 -912.09,983.73 CT24.2@-912.09,953.9
N18093: CT16.2 RT44.2 UT4.3 | length 129.6
  TOP w20: CT16.2@-1043.97,1005.9 -996.22,1005.9 UT4.3@-987.12,1015 -968.03,995.91 RT44.2@-968.03,953.9
N18488: CT25.1 RT45.2 RT46.1 | length 111.9
  TOP w20: RT45.2@-764.79,890.9 RT46.1@-708.85,890.9 CT25.1@-652.91,890.9
N18496: CT25.2 RT26.1 UT5.1 UT5.4 | length 738.9
  TOP w20: RT26.1@-1170,1293.72 -1108.72,1293.72 -1030,1215 -851.37,1215 -727.94,1091.57 UT5.1@-727.94,1089.8 -696.44,1089.8 UT5.4@-621.64,1015 -652.91,983.73 CT25.2@-652.91,953.9
N18568: CT17.2 RT46.2 UT5.3 | length 129.6
  TOP w20: CT17.2@-784.79,1005.9 -737.04,1005.9 UT5.3@-727.94,1015 -708.85,995.91 RT46.2@-708.85,953.9
N28683: CT27.2 RT15.1 RT59.2 UT7.1 | length 818.8
  TOP w20: RT59.2@656,862.69 CT27.2@656,917.69 656,1033.71 634.62,1055.09 UT7.1@599.35,1055.09 565,1089.44 565,1220 657,1312 RT15.1@930,1312
N28695: CT27.1 RT59.1 UT7.4 | length 123.1
  TOP w20: UT7.4@705.65,980.29 719,966.94 CT27.1@719,917.69 RT59.1@719,862.69
N28775: CT20.1 RT52.2 UT7.3 | length 125.4
  TOP w20: CT20.1@537.5,976.19 541.6,980.29 UT7.3@599.35,980.29 599.35,921.04 RT52.2@597.5,919.19
N28956: CT31.1 RT51.2 RT52.1 RT62.2 RT63.2 | length 226.3
  TOP w20: CT31.1@487.5,852.69 491,856.19 RT51.2@537.5,856.19 RT52.1@597.5,856.19 RT62.2@597.5,804.19 601,807.69 654,807.69 RT63.2@657.5,804.19
N31299: CT32.1 RT53.2 RT54.1 RT64.2 RT65.2 | length 226.3
  TOP w20: CT32.1@826.02,852.69 829.52,856.19 RT53.2@876.02,856.19 RT54.1@936.02,856.19 RT64.2@936.02,804.19 939.52,807.69 992.52,807.69 RT65.2@996.02,804.19
N31469: CT21.1 RT54.2 UT8.3 | length 125.4
  TOP w20: CT21.1@876.02,976.19 880.12,980.29 UT8.3@937.87,980.29 937.87,921.04 RT54.2@936.02,919.19
N31505: CT28.2 RT16.1 RT60.2 UT8.1 | length 558.8
  TOP w20: RT60.2@994.52,862.69 CT28.2@994.52,917.69 994.52,1033.71 973.14,1055.09 UT8.1@937.87,1055.09 937.87,1057.13 905,1090 905,1187 RT16.1@1030,1312
N31529: CT28.1 RT60.1 UT8.4 | length 123.1
  TOP w20: UT8.4@1044.17,980.29 1057.52,966.94 CT28.1@1057.52,917.69 RT60.1@1057.52,862.69
N32358: CT33.1 RT55.2 RT56.1 RT66.2 RT67.2 | length 226.3
  TOP w20: CT33.1@1164.54,852.69 1168.04,856.19 RT55.2@1214.54,856.19 RT56.1@1274.54,856.19 RT66.2@1274.54,804.19 1278.04,807.69 1331.04,807.69 RT67.2@1334.54,804.19
N32528: CT22.1 RT56.2 UT9.3 | length 125.4
  TOP w20: CT22.1@1214.54,976.19 1218.64,980.29 UT9.3@1276.39,980.29 1276.39,921.04 RT56.2@1274.54,919.19
N32564: CT29.2 RT17.1 RT61.2 UT9.1 | length 554.1
  TOP w20: RT17.1@1130,1312 1130,1201.48 UT9.1@1276.39,1055.09 1311.66,1055.09 1333.04,1033.71 CT29.2@1333.04,917.69 RT61.2@1333.04,862.69
N32588: CT29.1 RT61.1 UT9.4 | length 123.1
  TOP w20: UT9.4@1382.69,980.29 1396.04,966.94 CT29.1@1396.04,917.69 RT61.1@1396.04,862.69
N35636: RB23.2 RB24.1 | length 60.8
  BOTTOM w25: RB24.1@2955.68,472.82 RB23.2@3016.5,472.82
N35646: RB24.2 RB25.1 | length 60.8
  BOTTOM w25: RB25.1@2780.68,472.82 RB24.2@2841.5,472.82
N35650: RB25.2 RB26.1 | length 60.8
  BOTTOM w25: RB26.1@2605.68,472.82 RB25.2@2666.5,472.82
N35794: RT96.1 RT97.2 | length 60.8
  TOP w25: RT96.1@2955.68,252.82 RT97.2@3016.5,252.82
N35798: RT95.1 RT96.2 | length 60.8
  TOP w25: RT95.1@2780.68,252.82 RT96.2@2841.5,252.82
N35802: RT94.1 RT95.2 | length 60.8
  TOP w25: RT94.1@2605.68,252.82 RT95.2@2666.5,252.82
N35806: CT54.2 RT90.1 RT93.2 RT94.2 | length 343.8
  TOP w15: RT93.2@2253.5,252.82 2312.44,311.76 RT90.1@2316.5,311.76
  TOP w20: CT54.2@2196.5,252.82 RT93.2@2253.5,252.82
  TOP w25: RT90.1@2316.5,311.76 2318.26,310 2395,310 2452.18,252.82 RT94.2@2491.5,252.82
N45499: RT78.1 RT79.2 | length 60.8
  TOP w25: RT78.1@2955.68,711.88 RT79.2@3016.5,711.88
N45503: RT77.1 RT78.2 | length 60.8
  TOP w25: RT77.1@2780.68,711.88 RT78.2@2841.5,711.88
N45507: RT76.1 RT77.2 | length 60.8
  TOP w25: RT76.1@2605.68,711.88 RT77.2@2666.5,711.88
N45511: CT38.2 RT68.1 RT75.2 RT76.2 | length 343.8
  TOP w15: RT75.2@2253.5,711.88 2312.44,770.82 RT68.1@2316.5,770.82
  TOP w20: CT38.2@2196.5,711.88 RT75.2@2253.5,711.88
  TOP w25: RT68.1@2316.5,770.82 2317.32,770 2375,770 2433.12,711.88 RT76.2@2491.5,711.88
N45813: RB15.2 RB16.1 | length 60.8
  BOTTOM w25: RB16.1@2955.68,931.88 RB15.2@3016.5,931.88
N45817: RB16.2 RB17.1 | length 60.8
  BOTTOM w25: RB17.1@2780.68,931.88 RB16.2@2841.5,931.88
N45821: RB17.2 RB18.1 | length 60.8
  BOTTOM w25: RB18.1@2605.68,931.88 RB17.2@2666.5,931.88
N45825: CT36.1 RB18.2 RT40.1 RT58.1 | length 340.5
  TOP w20: CT36.1@2316.5,821.88 RT58.1@2316.5,876.88 RT40.1@2316.5,931.88
  TOP w25: RT58.1@2316.5,876.88 2316.88,876.5 v1(2491.5,876.5)
  BOTTOM w25: v1(2491.5,876.5) RB18.2@2491.5,931.88
N47166: RT32.1 RT33.2 | length 60.8
  TOP w25: RT32.1@2955.68,1170.94 RT33.2@3016.5,1170.94
N47170: RT31.1 RT32.2 | length 60.8
  TOP w25: RT31.1@2780.68,1170.94 RT32.2@2841.5,1170.94
N47174: RT30.1 RT31.2 | length 60.8
  TOP w25: RT30.1@2605.68,1170.94 RT31.2@2666.5,1170.94
N47178: CT6.2 RT28.1 RT29.2 RT30.2 | length 343.9
  TOP w15: RT29.2@2253.5,1170.94 2312.44,1229.88 RT28.1@2316.5,1229.88
  TOP w20: CT6.2@2196.5,1170.94 RT29.2@2253.5,1170.94
  TOP w25: RT28.1@2316.5,1229.88 2316.62,1230 2395,1230 2454.06,1170.94 RT30.2@2491.5,1170.94
N47480: RB9.2 RB10.1 | length 60.8
  BOTTOM w25: RB10.1@2955.68,1390.94 RB9.2@3016.5,1390.94
N47484: RB10.2 RB11.1 | length 60.8
  BOTTOM w25: RB11.1@2780.68,1390.94 RB10.2@2841.5,1390.94
N47488: RB11.2 RB12.1 | length 60.8
  BOTTOM w25: RB12.1@2605.68,1390.94 RB11.2@2666.5,1390.94
N47492: CT5.1 RB12.2 RT14.1 RT22.1 | length 346.3
  TOP w20: CT5.1@2316.5,1280.94 RT22.1@2316.5,1335.94 RT14.1@2316.5,1390.94
  TOP w25: RT22.1@2316.5,1335.94 2320.94,1331.5 v1(2491.5,1331.5)
  BOTTOM w25: v1(2491.5,1331.5) RB12.2@2491.5,1390.94
N51028: RT98.1 RT99.2 | length 60.8
  TOP w25: RT98.1@3305.68,252.82 RT99.2@3366.5,252.82
N51064: RB21.2 RB22.1 | length 60.8
  BOTTOM w25: RB22.1@3305.68,472.82 RB21.2@3366.5,472.82
N51070: RT97.1 RT98.2 | length 60.8
  TOP w25: RT97.1@3130.68,252.82 RT98.2@3191.5,252.82
N51074: RB22.2 RB23.1 | length 60.8
  BOTTOM w25: RB23.1@3130.68,472.82 RB22.2@3191.5,472.82
N51202: RT80.1 RT81.2 | length 60.8
  TOP w25: RT80.1@3305.68,711.88 RT81.2@3366.5,711.88
N51206: RT79.1 RT80.2 | length 60.8
  TOP w25: RT79.1@3130.68,711.88 RT80.2@3191.5,711.88
N51246: RB13.2 RB14.1 | length 60.8
  BOTTOM w25: RB14.1@3305.68,931.88 RB13.2@3366.5,931.88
